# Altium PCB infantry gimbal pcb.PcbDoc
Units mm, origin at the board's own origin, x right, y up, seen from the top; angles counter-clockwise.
Board outline 76 x 84 mm, 4 copper layers (SIGNAL, OTHER VCC, SHOOT VCC, GND), stack 0.604 mm thick; 16 components, 21 nets, 90 pads, 11 vias.
Unrouted connection lines stored in the file: 1.
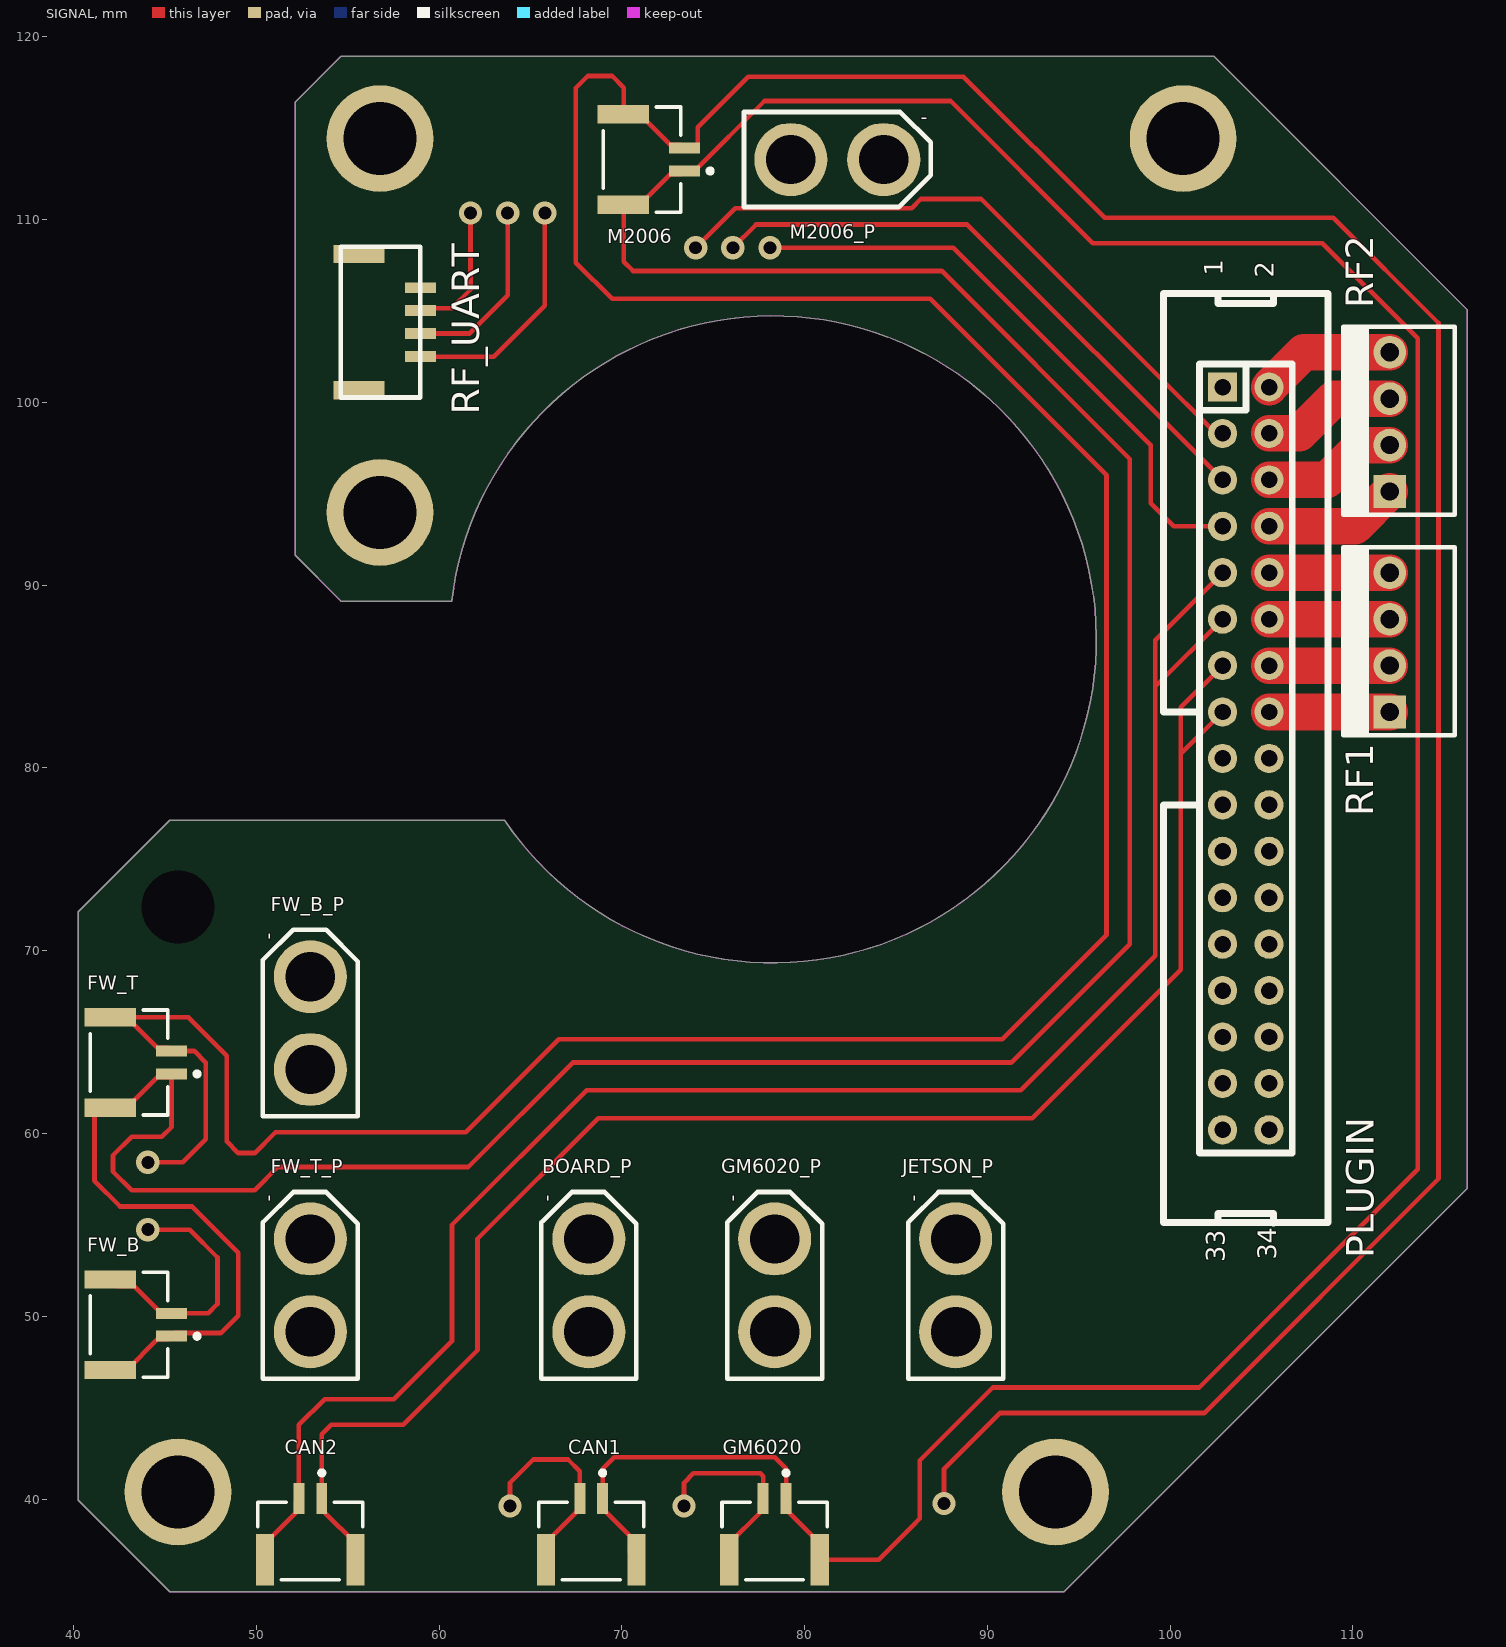
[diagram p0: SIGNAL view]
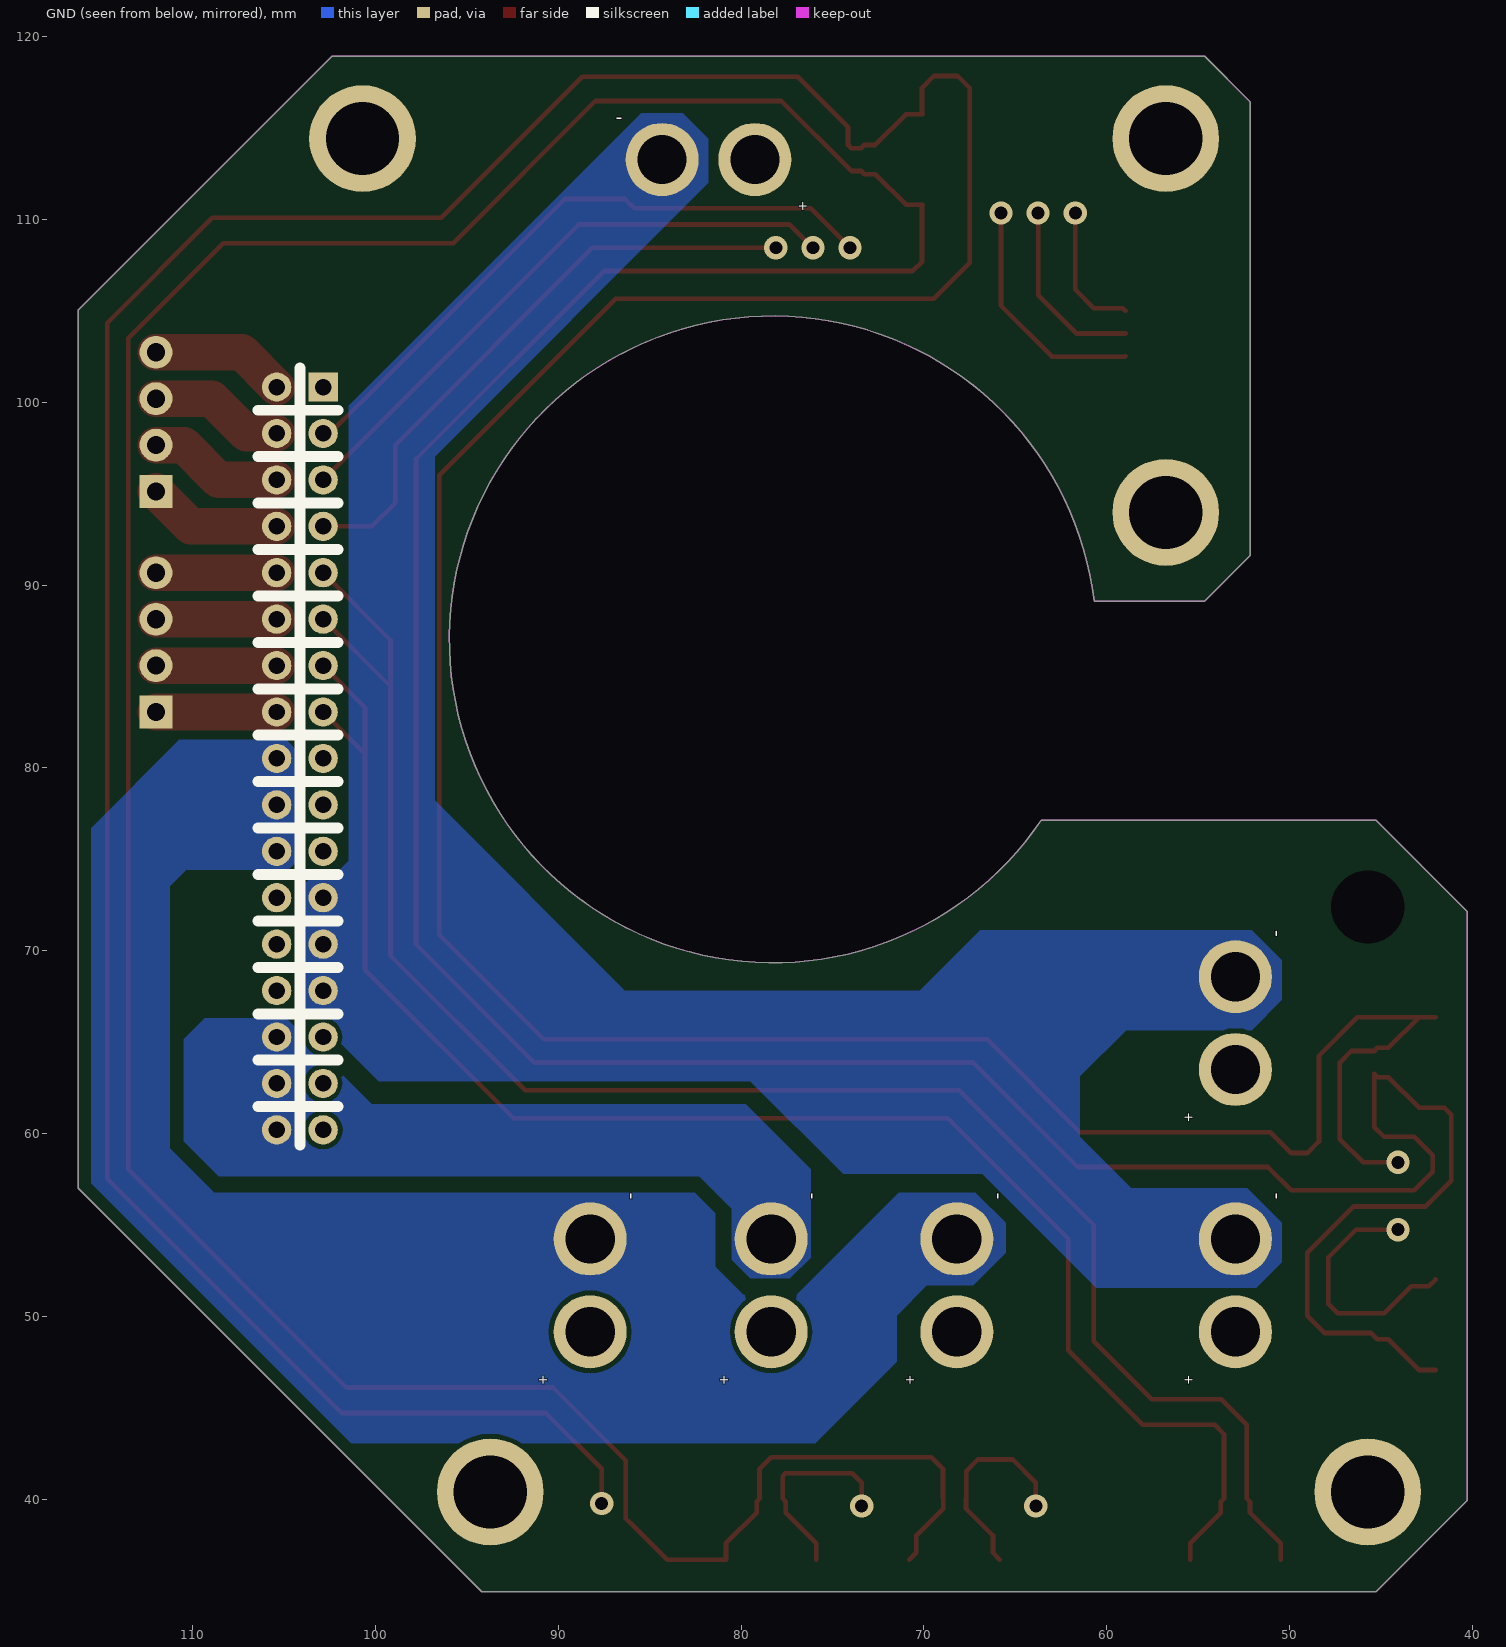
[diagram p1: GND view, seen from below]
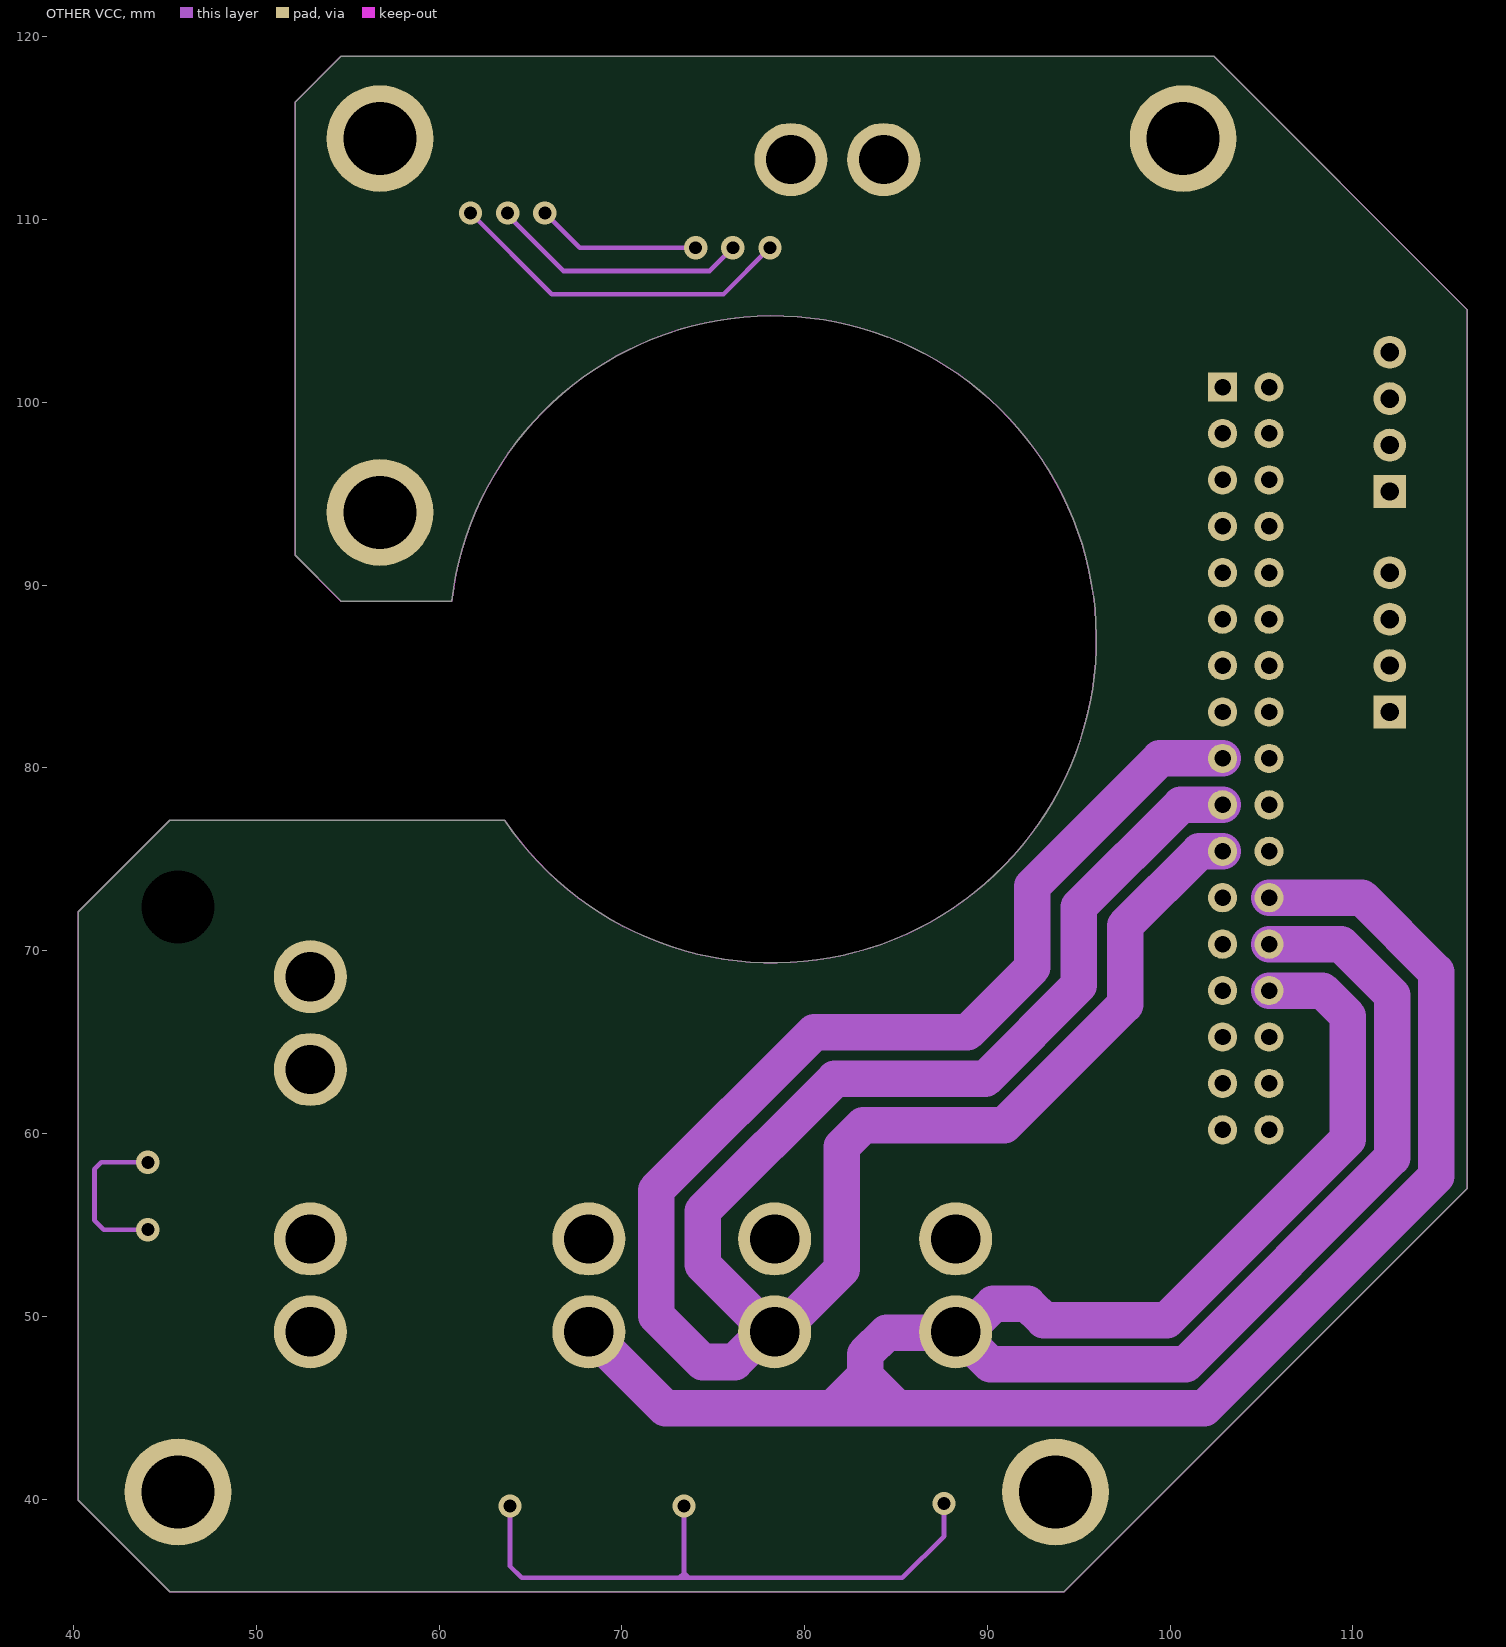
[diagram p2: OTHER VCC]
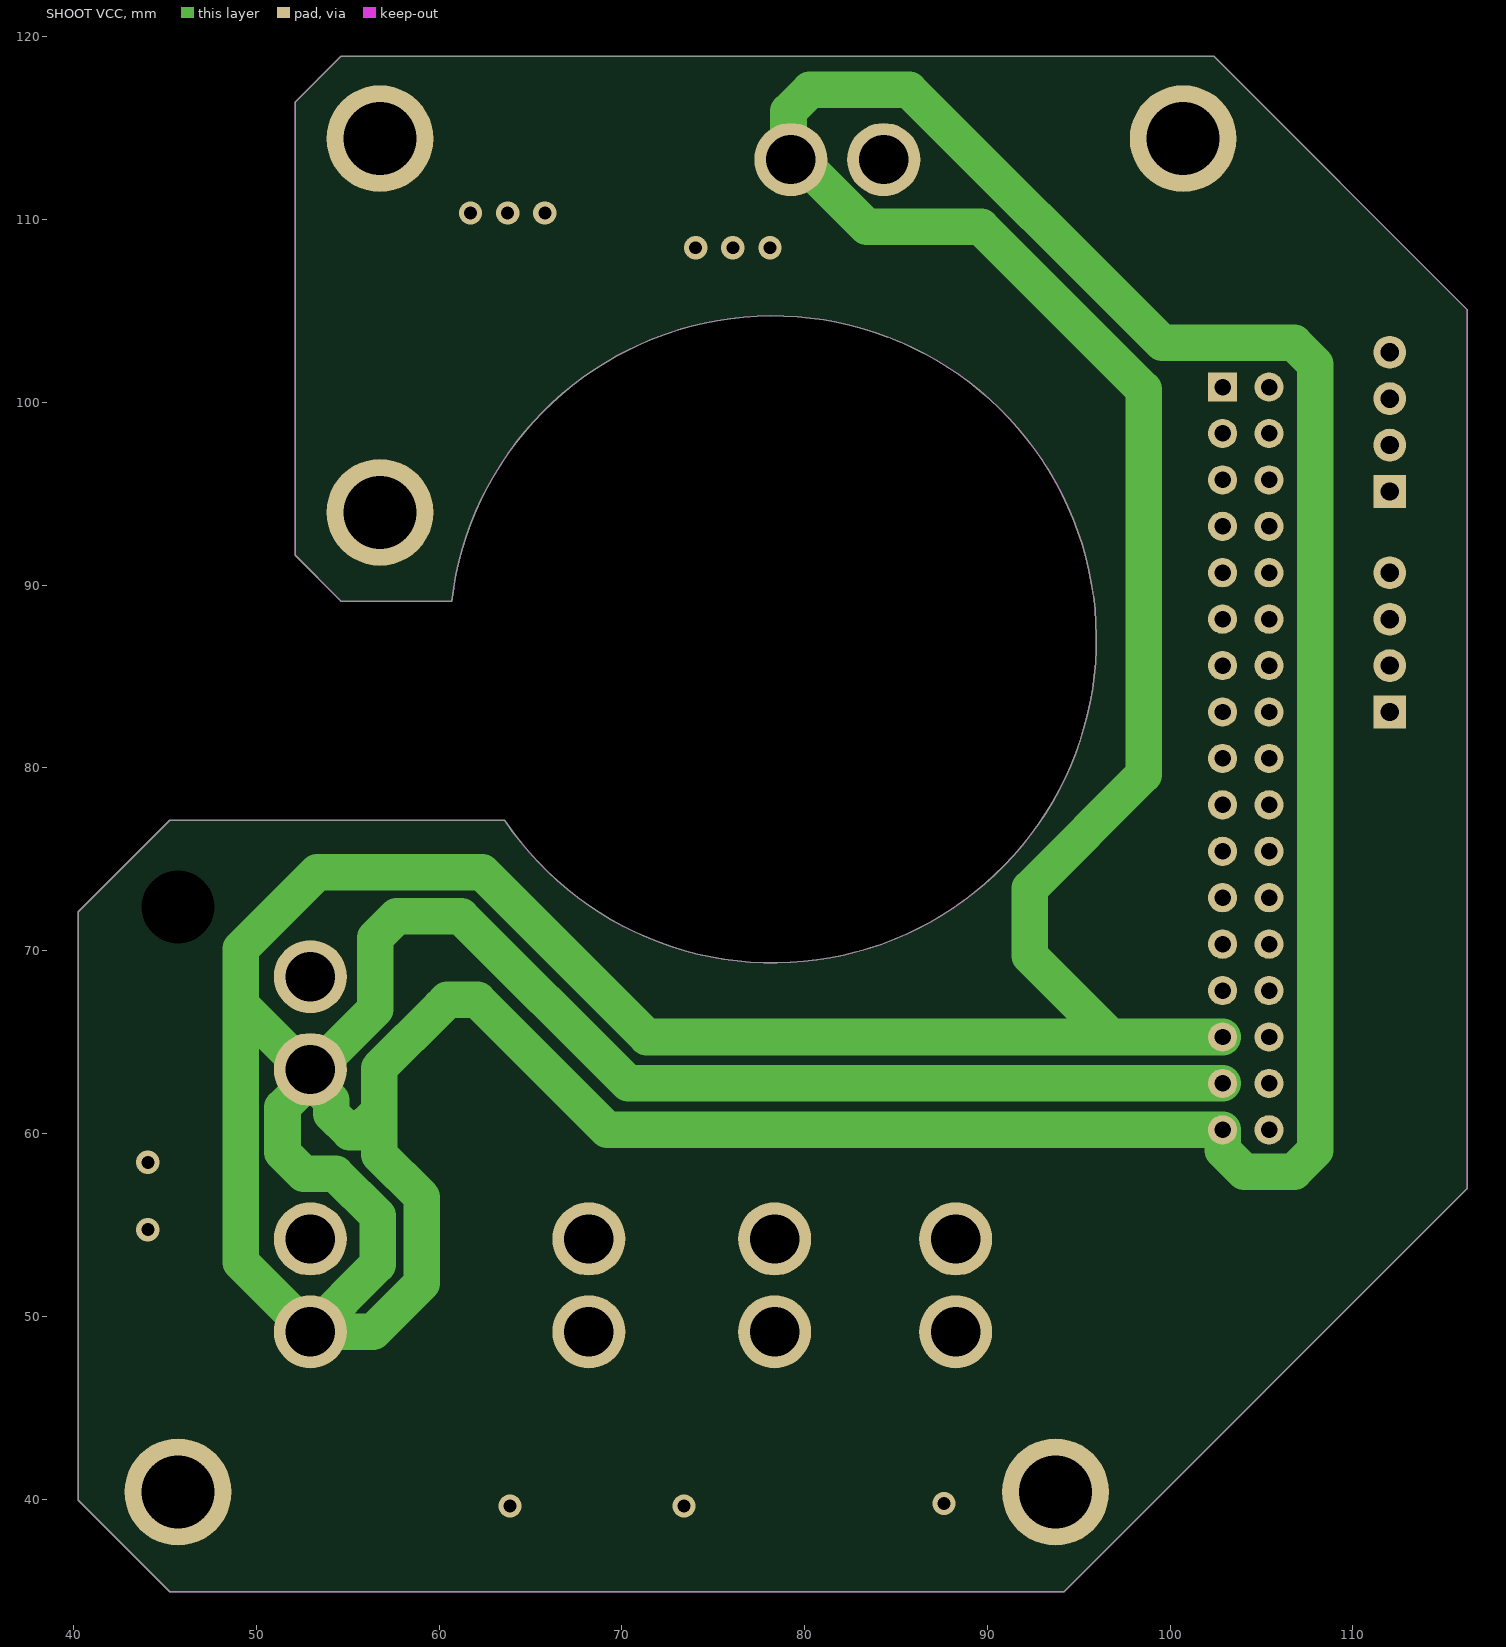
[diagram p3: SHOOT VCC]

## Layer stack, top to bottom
Top Solder: solder mask 0.611, Solder Resist, Dk 3.5
SIGNAL: signal copper 0.036
Dielectric 1: prepreg 0.071, PP-006, Dk 4.1
OTHER VCC: signal copper 0.035
Dielectric 2: dielectric 0.32, FR-4, Dk 4.8
SHOOT VCC: signal copper 0.035
Dielectric 3: prepreg 0.071, PP-006, Dk 4.1
GND: signal copper 0.036
Bottom Solder: solder mask 0.611, Solder Resist, Dk 3.5

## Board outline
40.265,39.931 40.265,72.131 45.265,77.131 63.593,77.131 ccw(c78.265,87.031) 60.69,89.131 54.637,89.131 52.137,91.631 52.137,116.431 54.637,118.931 102.394,118.931 116.265,105.06 116.265,57.002 94.194,34.931 45.265,34.931

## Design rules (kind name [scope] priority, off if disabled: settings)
Clearance [All] p1: gap=0.254 ignorepadtopadclearanceinfootprint=FALSE except(0: Arc-Hole Track-Hole SMDPad-Hole THPad-Hole Via-Hole Fill-Hole Poly-Hole Region-Hole Text-Hole)
PlaneConnect [All] p1: planeconnectstyle=Direct reliefexpansion=0.508 reliefentries=4 reliefconductorwidth=0.254 reliefairgap=0.254
PolygonConnect [All] p1: connectstyle=Direct reliefconductorwidth=0.254 reliefentries=4 polygonreliefangle="90 Angle" airgapwidth=0.254
RoutingVias [All] p1: holewidth=0.711 width=1.27 viastyle="Through Hole" minholewidth=0.711 minwidth=1.27 maxholewidth=0.711 maxwidth=1.27
SolderMaskExpansion [All] p1: expansion=0.102 istentingtop=FALSE
Width [All] p1: maxlimit=10 minlimit=0.254 preferedwidth=2 toplayer_maxwidth=2 toplayer_prefwidth=0.254 midlayer1_maxwidth=2 midlayer2_maxwidth=2 bottomlayer_minwidth=2 minimp=50.000000 maximp=50.000000 favimp=50.000000
29 further rules are at their usual default settings.

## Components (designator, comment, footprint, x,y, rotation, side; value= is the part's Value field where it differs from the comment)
BOARD_P "XT PLUGIN" XT30-M 68.199,51.689 r90 top
CAN1 "CAN1" JST-BM02B-GHS-TBT_V 68.326,38.354 r180 top
CAN2 "CAN2" JST-BM02B-GHS-TBT_V 52.959,38.354 r180 top
FW_B "CAN1" JST-BM02B-GHS-TBT_V 43.688,49.533 r90 top
FW_B_P "XT PLUGIN" XT30-M 52.959,66.04 r90 top
FW_T "CAN1" JST-BM02B-GHS-TBT_V 43.688,63.884 r90 top
FW_T_P "XT PLUGIN" XT30-M 52.959,51.689 r90 top
GM6020 "CAN1" JST-BM02B-GHS-TBT_V 78.359,38.354 r180 top
GM6020_P "XT PLUGIN" XT30-M 78.359,51.689 r90 top
JETSON_P "XT PLUGIN" XT30-M 88.265,51.689 r90 top
M2006 "CAN1" JST-BM02B-GHS-TBT_V 71.755,113.284 r90 top
M2006_P "XT PLUGIN" XT30-M 81.788,113.284 r0 top
PLUGIN "Header 2X11" IDC2.54-LI-2x17P 102.87,100.838 r270 top
RF1 "HDR-1X4" KF2510-LI-4P 112.014,86.868 r90 top
RF2 "HDR-1X4" KF2510-LI-4P 112.014,98.933 r90 top
RF_UART "gh1.25 P4" GH1.25-4PIN 55.626,104.394 r270 top

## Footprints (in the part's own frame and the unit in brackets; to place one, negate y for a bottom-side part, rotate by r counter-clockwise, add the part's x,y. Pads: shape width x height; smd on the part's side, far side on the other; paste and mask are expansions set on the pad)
GH1.25-4PIN [mm]
  rect 1x2.8 smd: 1(-3.725,0) 4(3.725,0)
  rect 0.6x1.7 smd: 1(-1.875,3.35) 2(-0.625,3.35) 3(0.625,3.35) 4(1.875,3.35)
  silkscreen extent -4.13,-1 4.13,3.35
IDC2.54-LI-2x17P [mm] "34P简易牛角座"
  rect 1.6x1.6 hole 0.9: 1(0,0)
  round 1.6 hole 0.9: 2(0,2.54) 3(2.54,0) 4(2.54,2.54) 5(5.08,0) 6(5.08,2.54) 7(7.62,0) 8(7.62,2.54) 9(10.16,0) 10(10.16,2.54) 11(12.7,0) 12(12.7,2.54) 13(15.24,0) 14(15.24,2.54) 15(17.78,0) 16(17.78,2.54) 17(20.32,0) 18(20.32,2.54) 19(22.86,0) 20(22.86,2.54) 21(25.4,0) 22(25.4,2.54) 23(27.94,0) 24(27.94,2.54) 25(30.48,0) 26(30.48,2.54) 27(33.02,0) 28(33.02,2.54) 29(35.56,0) 30(35.56,2.54) 31(38.1,0) 32(38.1,2.54) 33(40.64,0) 34(40.64,2.54)
  silkscreen extent -5.11,-3.23 45.75,5.77, body extent -5.08,-3.08 45.72,5.77, height 9.17
JST-BM02B-GHS-TBT_V [mm] "Connector, 2-Leads, Body 5.75x4.25mm, Pitch 1.25mm"
  rect 0.6x1.7 smd: 1(-0.625,-1.675) 2(0.625,-1.675)
  rect 1x2.8 smd: MP1(-2.475,1.675) MP2(2.475,1.675)
  silkscreen extent -2.88,-3.2 2.88,2.78, body extent -2.88,-2.17 2.87,2.78, height 4.21
KF2510-LI-4P [mm] "接插件/2A"
  rect 1.8x1.8 hole 1: 1(-3.81,0)
  round 1.8 hole 1: 2(-1.27,0) 3(1.27,0) 4(3.81,0)
  silkscreen extent -5.08,-3.56 5.21,2.54, body extent -5.08,-3.5 5.08,2.4, height 11.05
XT30-M [mm]
  round 4 hole 2.7: 1(-2.54,0) 2(2.54,0)
  silkscreen extent -5.1,-2.6 5.11,2.6, body extent -5.18,-2.8 5.02,2.8, height 10.66

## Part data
CAN1 CAN2 FW_B FW_T GM6020 M2006: library part CMP-2000-05957-1, "Disconnectable Crimp Style Connector, Pitch 1.25 mm, 1 x 2 Position, Height 4.05 mm, -25 to 85 degC, RoHS, Tape and Reel", Color=Natural, Manufacturer=JST-Sales-America-Inc., Package Description="Disconnectable Crimp Style Connector, Pitch 1.25 mm, 1 x 2 Position, Height 4.05 mm", Package Reference=BM02B-GHS-TBT
PLUGIN: library part "Header 17X2", "17*2P接插件"
RF1 RF2: library part "Header 4", "4P接插件"

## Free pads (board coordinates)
  round 5.842 hole 4: 7(45.72,40.386) 8(93.726,40.386) 9(56.769,93.98) 10(56.769,114.427) 11(100.711,114.427)
  round 3.81 hole 4: 12(45.72,72.39)

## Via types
v1: diameter 1.27/1.27/1.27/1.27 (per signal layer), hole 0.711, SIGNAL to GND, 6 vias
v2: diameter 1.27, hole 0.711, SIGNAL to GND, 5 vias

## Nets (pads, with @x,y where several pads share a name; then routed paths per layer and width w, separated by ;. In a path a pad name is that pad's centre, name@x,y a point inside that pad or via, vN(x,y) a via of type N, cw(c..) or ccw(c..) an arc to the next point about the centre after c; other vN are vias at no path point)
AMMO_DC: FW_B_P.1 FW_T_P.1 M2006_P.1 PLUGIN.29 PLUGIN.31 PLUGIN.33 | length 395.3
  SHOOT VCC w2: PLUGIN.31 70.358,62.738 61.214,71.882 57.687,71.882 56.515,70.71 56.515,66.802 53.213,63.5 FW_B_P.1 ; PLUGIN.29 96.774,65.278 ; 49.149,67.056 49.149,52.959 FW_T_P.1 ; 49.149,67.056 49.149,70.104 53.34,74.295 62.357,74.295 71.374,65.278 96.774,65.278 ; 49.149,67.056 52.705,63.5 FW_B_P.1 ; FW_T_P.1 56.642,52.832 56.642,55.499 54.345,57.796 52.607,57.796 51.435,58.968 51.435,61.435 FW_B_P.1@52.959,62.959 ; FW_T_P.1 56.388,49.149 59.055,51.816 59.055,56.515 56.719,58.851 56.719,61.214 ; FW_B_P.1@52.959,62.959 FW_B_P.1 ; FW_B_P.1@52.959,62.959 54.102,61.816 54.102,61.087 55.118,60.071 55.576,60.071 56.719,61.214 ; 56.719,61.214 56.719,63.577 60.071,66.929 60.449,67.307 62.106,67.307 69.215,60.198 PLUGIN.33 102.87,59.084 104.042,57.912 106.778,57.912 107.95,59.084 107.95,102.079 106.778,103.251 99.568,103.251 85.725,117.094 80.293,117.094 79.121,115.922 79.121,113.411 M2006_P.1 79.726,113.284 83.409,109.601 89.662,109.601 98.552,100.711 98.552,79.629 92.329,73.406 92.329,69.723 96.774,65.278
AMMO_GND: FW_B_P.2 FW_T_P.2 M2006_P.2 PLUGIN.23 PLUGIN.25 PLUGIN.27
CAN1_H: CAN1.2 CAN1.MP2 FW_B.2 FW_B.MP2 FW_T.2 FW_T.MP2 GM6020.2 GM6020.MP2 M2006.2 M2006.MP2 | length 367.1
  SIGNAL w0.254: FW_B.MP2 42.386,51.635 43.336,51.635 44.813,50.158 FW_B.2 45.37,50.165 47.371,50.165 47.879,50.673 47.879,53.213 46.391,54.701 ; FW_T.MP2 FW_T.MP2@42.913,66.359 ; v2(44.069,54.737) 46.355,54.737 ; v2(44.069,58.42) 45.974,58.42 47.244,59.69 47.244,63.881 46.609,64.516 45.37,64.516 FW_T.2 45.19,64.682 44.59,64.682 FW_T.MP2@42.913,66.359 ; v2(63.881,39.624) 63.881,40.894 65.151,42.164 67.056,42.164 67.691,41.529 67.691,40.039 CAN1.2 67.701,39.479 66.224,38.002 66.224,37.052 CAN1.MP2 ; v2(73.406,39.624) 73.406,40.894 73.914,41.402 77.585,41.402 77.734,41.253 GM6020.2 77.561,39.856 77.561,39.256 75.884,37.579 GM6020.MP2 ; v2(87.63,39.751) 87.63,41.656 90.678,44.704 101.854,44.704 114.681,57.531 114.681,104.34 108.93,110.091 96.411,110.091 88.691,117.811 76.917,117.811 74.153,115.047 74.153,114.082 73.98,113.909 M2006.2 73.257,114.082 72.657,114.082 70.98,115.759 M2006.MP2 70.104,115.783 70.104,117.221 69.469,117.856 68.146,117.856 67.487,117.197 67.487,107.646 69.469,105.664 86.868,105.664 96.52,96.012 96.52,70.866 90.805,65.151 66.548,65.151 61.468,60.071 51.054,60.071 49.911,58.928 49.022,58.928 48.387,59.563 48.387,64.262 46.29,66.359 FW_T.MP2@42.913,66.359
  OTHER VCC w0.254: v2(44.069,54.737) 41.656,54.737 41.148,55.245 41.148,58.039 41.529,58.42 v2(44.069,58.42) ; v2(63.881,39.624) 63.881,36.322 64.516,35.687 73.152,35.687 ; v2(73.406,39.624) 73.406,35.941 ; v2(87.63,39.751) 87.63,37.973 85.344,35.687 73.66,35.687 ; 73.152,35.687 73.66,35.687 ; 73.152,35.687 73.406,35.941 ; 73.406,35.941 73.66,35.687
CAN1_L: CAN1.1 CAN1.MP1 FW_B.1 FW_B.MP1 FW_T.1 FW_T.MP1 GM6020.1 GM6020.MP1 M2006.1 M2006.MP1 | length 323.1
  SIGNAL w0.254: FW_B.MP1 42.913,47.058 44.59,48.735 45.19,48.735 FW_B.1 45.536,49.081 48.065,49.081 49.022,50.038 49.022,53.467 46.482,56.007 42.545,56.007 41.148,57.404 41.148,61.036 41.521,61.409 42.913,61.409 44.59,63.086 45.19,63.086 FW_T.1 45.363,60.349 44.831,59.817 43.18,59.817 42.164,58.801 42.164,57.912 43.18,56.896 49.911,56.896 51.181,58.166 61.595,58.166 67.31,63.881 91.313,63.881 97.79,70.358 97.79,96.901 87.503,107.188 70.612,107.188 70.104,107.696 70.104,110.785 M2006.MP1 70.98,110.809 72.657,112.486 73.257,112.486 M2006.1 73.98,112.659 77.806,116.485 87.985,116.485 95.758,108.712 108.331,108.712 113.538,103.505 113.538,58.039 101.6,46.101 90.297,46.101 86.306,42.11 86.306,38.935 85.852,38.481 84.05,36.679 GM6020.MP1 80.834,37.579 79.157,39.256 79.157,39.856 GM6020.1 78.994,40.039 78.994,41.656 78.359,42.291 69.596,42.291 68.961,41.656 68.961,40.039 CAN1.1 68.951,39.479 70.428,38.002 70.428,37.052 CAN1.MP1
CAN2_H: CAN2.2 CAN2.MP2 PLUGIN.9 PLUGIN.11 | length 97
  SIGNAL w0.254: CAN2.MP2 50.484,37.579 52.161,39.256 52.161,39.856 CAN2.2 52.334,44.059 53.741,45.466 57.531,45.466 60.706,48.641 60.706,54.991 68.072,62.357 91.821,62.357 99.187,69.723 99.187,84.455 ; PLUGIN.11 99.187,84.455 ; PLUGIN.9 99.187,86.995 99.187,84.455
CAN2_L: CAN2.1 CAN2.MP1 PLUGIN.13 PLUGIN.15 | length 89.6
  SIGNAL w0.254: CAN2.MP1 55.434,37.579 53.757,39.256 53.757,39.856 CAN2.1 53.584,43.551 54.102,44.069 58.039,44.069 62.103,48.133 62.103,54.229 68.707,60.833 92.456,60.833 100.584,68.961 100.584,80.772 ; PLUGIN.15 100.584,80.772 ; PLUGIN.13 100.584,83.312 100.584,80.772
GMB_DC: GM6020_P.1 PLUGIN.17 PLUGIN.19 PLUGIN.21 | length 148.6
  OTHER VCC w2: PLUGIN.21 101.6,75.438 97.536,71.374 97.536,67.056 90.932,60.452 83.214,60.452 82.042,59.28 82.042,52.578 78.613,49.149 GM6020_P.1 GM6020_P.1@78.105,49.149 ; PLUGIN.19 100.584,77.978 94.996,72.39 94.996,68.099 89.889,62.992 81.661,62.992 74.422,55.753 74.422,52.832 GM6020_P.1@78.105,49.149 ; PLUGIN.17 99.441,80.518 92.456,73.533 92.456,69.088 88.9,65.532 80.518,65.532 71.882,56.896 71.882,50.038 74.422,47.498 76.167,47.498 77.818,49.149 GM6020_P.1@78.105,49.149
GMB_GND: GM6020_P.2 PLUGIN.30 PLUGIN.32 PLUGIN.34
MPC_DC: BOARD_P.1 JETSON_P.1 PLUGIN.24 PLUGIN.26 PLUGIN.28 | length 171.2
  OTHER VCC w2: BOARD_P.1 72.39,44.958 81.534,44.958 ; PLUGIN.28 108.331,67.818 109.728,66.421 109.728,59.69 99.822,49.784 93.091,49.784 92.202,50.673 90.33,50.673 88.806,49.149 JETSON_P.1@88.392,49.149 ; PLUGIN.26 109.347,70.358 112.141,67.564 112.141,58.674 100.838,47.371 90.17,47.371 JETSON_P.1@88.392,49.149 ; PLUGIN.24 110.49,72.898 114.554,68.834 114.554,57.658 101.854,44.958 85.09,44.958 ; 81.534,44.958 85.09,44.958 ; 81.534,44.958 83.312,46.736 ; 83.312,46.736 85.09,44.958 ; 83.312,46.736 83.312,47.926 84.484,49.097 88.213,49.097 JETSON_P.1 JETSON_P.1@88.392,49.149
MPC_GND: BOARD_P.2 JETSON_P.2 PLUGIN.18 PLUGIN.20 PLUGIN.22
Referee_1A: PLUGIN.10 RF1.4 | length 6.6
  SIGNAL w2: PLUGIN.10 RF1.4
Referee_1B: PLUGIN.12 RF1.3 | length 6.6
  SIGNAL w2: PLUGIN.12 RF1.3
Referee_1C: PLUGIN.14 RF1.2 | length 6.6
  SIGNAL w2: PLUGIN.14 RF1.2
Referee_1D: PLUGIN.16 RF1.1 | length 6.6
  SIGNAL w2: PLUGIN.16 RF1.1
Referee_2A: PLUGIN.2 RF2.4 | length 7.4
  SIGNAL w2: PLUGIN.2 107.315,102.743 RF2.4
Referee_2B: PLUGIN.4 RF2.3 | length 7.4
  SIGNAL w2: PLUGIN.4 107.061,98.298 108.966,100.203 RF2.3
Referee_2C: PLUGIN.6 RF2.2 | length 7.4
  SIGNAL w2: PLUGIN.6 108.585,95.758 110.49,97.663 RF2.2
Referee_2D: PLUGIN.8 RF2.1 | length 7.4
  SIGNAL w2: PLUGIN.8 110.109,93.218 RF2.1
UART_GND: PLUGIN.7 RF_UART.2 | length 59.6
  SIGNAL w0.254: RF_UART.2 59.113,105.156 60.706,105.156 61.722,106.172 v1(61.722,110.363) ; v1(78.105,108.458) 88.138,108.458 98.933,97.663 98.933,94.488 100.203,93.218 PLUGIN.7
  OTHER VCC w0.254: v1(61.722,110.363) 66.167,105.918 75.565,105.918 v1(78.105,108.458)
UART_RX: PLUGIN.3 RF_UART.4 | length 57.4
  SIGNAL w0.254: RF_UART.4@58.976,102.519 59.006,102.489 62.992,102.489 65.786,105.283 v1(65.786,110.363) ; v1(74.041,108.458) 76.2,110.617 85.852,110.617 86.36,111.125 89.662,111.125 100.838,99.949 100.855,99.949 102.506,98.298 PLUGIN.3
  OTHER VCC w0.254: v1(65.786,110.363) 67.691,108.458 v1(74.041,108.458)
UART_Tx: PLUGIN.5 RF_UART.3 | length 57.5
  SIGNAL w0.254: RF_UART.3 61.674,103.769 63.754,105.849 v1(63.754,110.363) ; v1(76.073,108.458) 77.343,109.728 88.9,109.728 PLUGIN.5
  OTHER VCC w0.254: v1(63.754,110.363) 63.754,110.236 66.802,107.188 74.803,107.188 v1(76.073,108.458)
pads on no net: PLUGIN.1 RF_UART.1

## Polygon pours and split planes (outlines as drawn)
MPC_GND on GND "MPC_GND_L04_P006" (solid, pour order 6): 82.55,56.769 81.407,55.626 81.407,52.705 79.883,51.181 76.962,51.181 71.374,56.769 67.183,56.769 65.532,55.118 65.532,53.467 67.31,51.689 69.85,51.689 71.501,50.038 71.501,47.498 75.946,43.053 101.346,43.053 115.57,57.277 115.57,76.708 110.744,81.534 104.902,81.534 104.14,80.772 104.14,75.057 104.775,74.422 110.363,74.422 111.252,73.533 111.252,59.182 108.839,56.769
AMMO_GND on GND "AMMO_GND_L04_P008" (solid, pour order 8): 52.07,71.12 50.419,69.469 50.419,67.31 52.07,65.659 58.928,65.659 61.468,63.119 61.468,59.817 58.653,57.002 52.303,57.002 50.419,55.118 50.419,52.959 51.816,51.562 60.579,51.562 66.802,57.785 74.422,57.785 79.502,62.865 99.822,62.865 104.013,67.056 104.013,73.533 103.378,74.168 102.235,74.168 101.473,74.93 101.473,99.822 85.471,115.824 83.185,115.824 81.788,114.427 81.788,112.014 96.774,97.028 96.774,78.232 86.36,67.818 70.231,67.818 66.929,71.12
GMB_GND on GND "GMB_GND_L04_P000" (solid, pour order 0): 76.2,53.213 77.343,52.07 79.502,52.07 80.518,53.086 80.518,55.88 82.296,57.658 108.585,57.658 110.49,59.563 110.49,65.151 109.347,66.294 104.902,66.294 100.203,61.595 79.756,61.595 76.2,58.039

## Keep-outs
Keep-Out Layer:
  the board outline again, w0.013

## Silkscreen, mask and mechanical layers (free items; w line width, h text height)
Mechanical 1:
  the board outline again, w0.2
